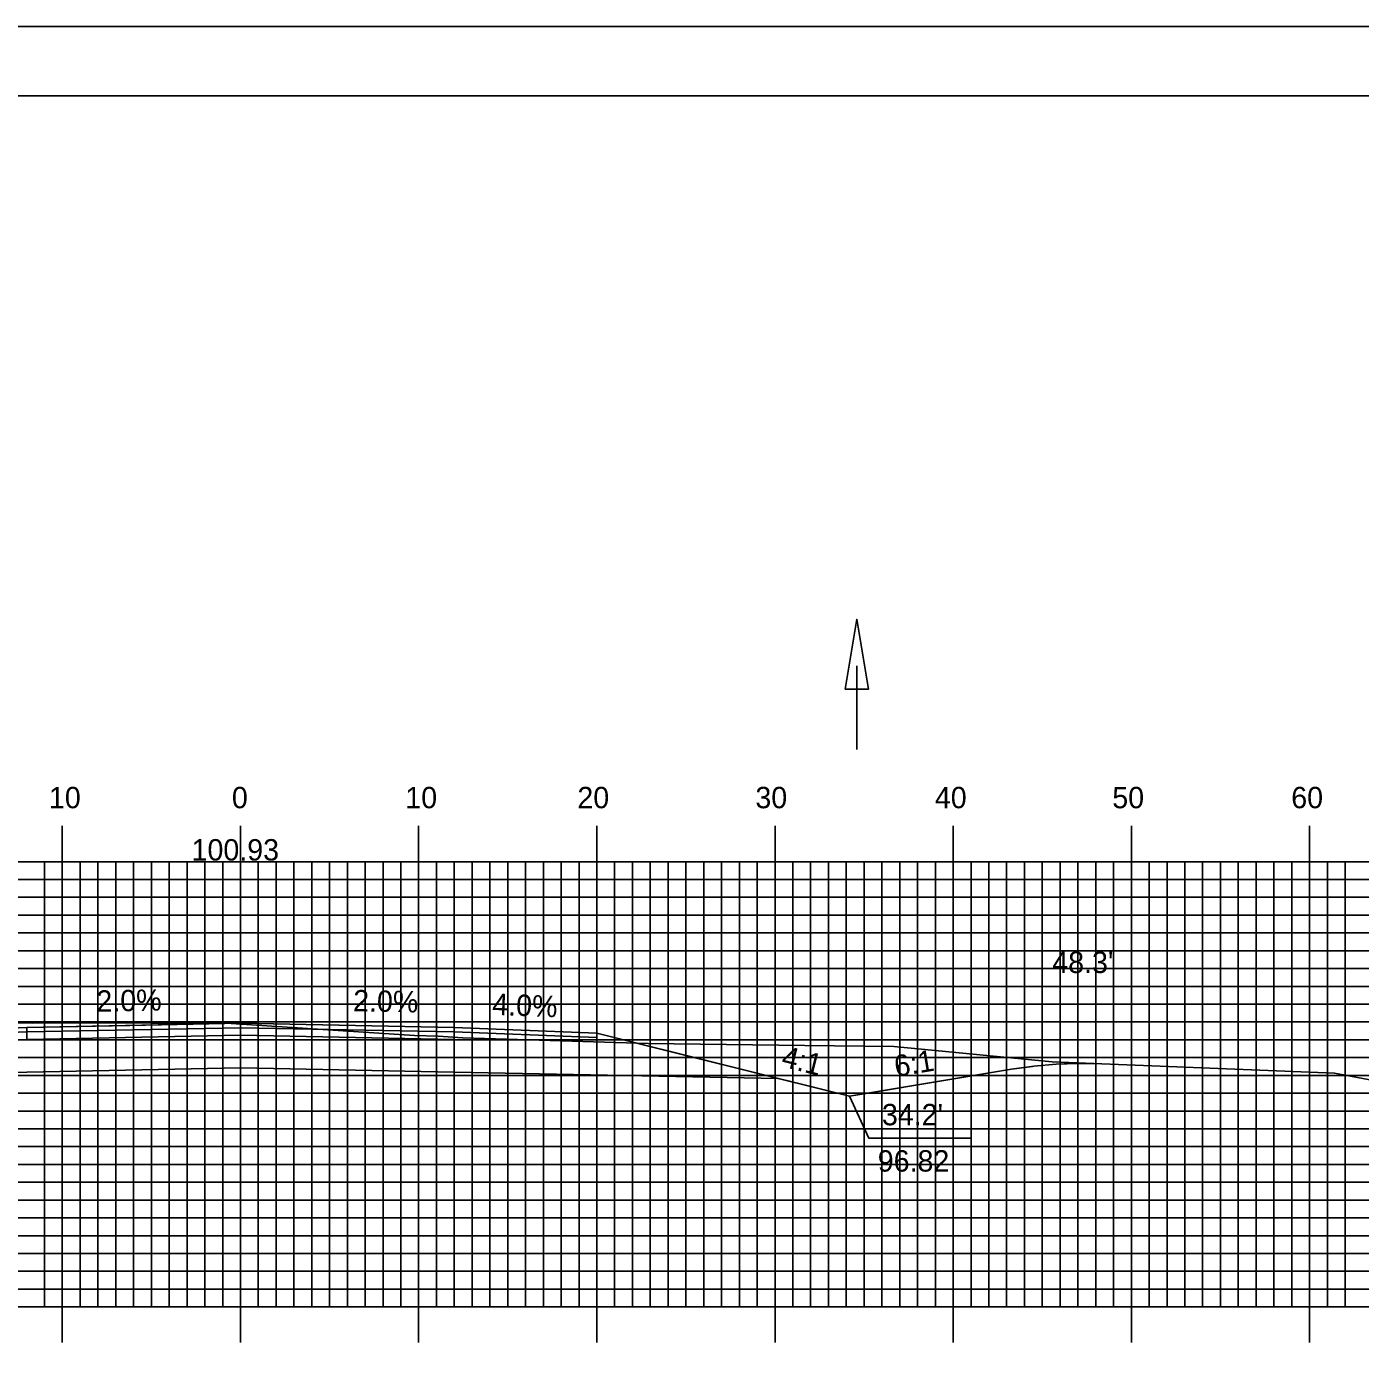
# Model space of a CAD drawing. Extents: x 1774777 to 1775120, y 442591 to 442811.
# Drawn here: x 1774930.7 to 1775005.5, y 442736.2 to 442810.5 of the extents above; entities that cross this region are included whole.
import ezdxf

# ---------------------------------------------------------------- set-up
doc = ezdxf.new("R2010")
doc.units = 0
for name, color, linetype in [('ANNOTATION', 7, 'Continuous'), ('BORDER', 7, 'Continuous'), ('D_Drainage_Ditch_Line', 7, 'Continuous'), ('D_Roadway_Centerline', 7, 'Continuous'), ('D_Roadway_Centerline_Text', 7, 'Continuous'), ('D_Roadway_Edge_Shoulder', 7, 'Continuous'), ('D_Roadway_Edge_TW', 7, 'Continuous'), ('D_Roadway_Pavement', 7, 'Continuous'), ('D_Roadway_SlopeLines', 7, 'Continuous'), ('D_Roadway_SubGrade', 7, 'Continuous'), ('D_Text_Standard', 7, 'Continuous'), ('H_V ANNOTATION', 7, 'Continuous'), ('MAJOR', 7, 'Continuous'), ('MINOR', 7, 'Continuous'), ('PLOT BOUNDARY', 7, 'Continuous'), ('S_Roadway_Centerline', 7, 'Continuous')]:
    doc.layers.add(name, color=color, linetype=linetype)

msp = doc.modelspace()

# ---------------------------------------------------------------- linework, layer by layer
at = {"layer": 'ANNOTATION'}
msp.add_lwpolyline([(1774983.643, 442748.137), (1774977.952, 442748.137), (1774976.859, 442750.49)], dxfattribs=at)
at = {"layer": 'BORDER'}
msp.add_lwpolyline([(1774793.085, 442596.665), (1775113.085, 442596.665), (1775113.085, 442806.665), (1774793.085, 442806.665)], close=True, dxfattribs=at)
at = {"layer": 'D_Drainage_Ditch_Line'}
msp.add_line((1774977.274, 442774.655), (1774977.274, 442769.956), dxfattribs=at)
msp.add_lwpolyline([(1774976.618, 442773.342), (1774977.93, 442773.342), (1774977.274, 442777.279)], close=True, dxfattribs=at)
at = {"layer": 'D_Roadway_Centerline'}
msp.add_lwpolyline([(1774922.685, 442754.034), (1774930.685, 442754.354), (1774936.47, 442754.47), (1774942.685, 442754.594), (1774947.294, 442754.502), (1774954.685, 442754.354), (1774962.685, 442754.034), (1774966.715, 442753.027), (1774972.859, 442751.49), (1774976.859, 442750.49), (1774977.909, 442750.665), (1774985.965, 442752.008), (1774987.141, 442752.173), (1774987.214, 442752.183), (1774988.464, 442752.294), (1774989.356, 442752.327), (1774989.715, 442752.34), (1774990.247, 442752.333), (1774990.964, 442752.322)], dxfattribs=at)
at = {"layer": 'D_Roadway_Edge_Shoulder'}
for points in [[(1774930.685, 442754.354), (1774922.685, 442754.034), (1774922.685, 442753.784), (1774930.685, 442754.104)], [(1774954.685, 442754.354), (1774962.685, 442754.034), (1774962.685, 442753.784), (1774954.685, 442754.104)]]:
    msp.add_lwpolyline(points, close=True, dxfattribs=at)
at = {"layer": 'D_Roadway_Edge_TW'}
msp.add_lwpolyline([(1774930.685, 442754.104), (1774930.685, 442754.354), (1774942.685, 442754.594), (1774954.685, 442754.354), (1774954.685, 442754.104), (1774942.685, 442754.344)], close=True, dxfattribs=at)
at = {"layer": 'D_Roadway_Pavement'}
msp.add_lwpolyline([(1774930.685, 442753.687), (1774930.685, 442754.104), (1774942.685, 442754.344), (1774954.685, 442754.104), (1774954.685, 442753.687), (1774942.685, 442753.927)], close=True, dxfattribs=at)
at = {"layer": 'D_Roadway_SlopeLines'}
for points in [[(1774962.685, 442754.034), (1774976.859, 442750.49)], [(1774976.859, 442750.49), (1774985.964, 442752.008), (1774987.214, 442752.183), (1774988.464, 442752.294), (1774989.715, 442752.34), (1774990.964, 442752.322)]]:
    msp.add_lwpolyline(points, dxfattribs=at)
at = {"layer": 'D_Roadway_SubGrade'}
msp.add_lwpolyline([(1774930.685, 442751.854), (1774912.511, 442751.49), (1774922.685, 442754.034), (1774922.685, 442753.784), (1774930.685, 442754.104), (1774942.685, 442754.344), (1774954.685, 442754.104), (1774962.685, 442753.784), (1774962.685, 442754.034), (1774972.859, 442751.49), (1774954.685, 442751.854), (1774942.685, 442752.094)], close=True, dxfattribs=at)
at = {"layer": 'MAJOR'}
for p, q in [((1774932.685, 442765.669), (1774932.685, 442763.665)), ((1774942.685, 442765.669), (1774942.685, 442763.665)), ((1774952.685, 442765.669), (1774952.685, 442763.665)), ((1774962.685, 442765.669), (1774962.685, 442763.665)), ((1774972.685, 442765.669), (1774972.685, 442763.665)), ((1774982.685, 442765.669), (1774982.685, 442763.665)), ((1774992.685, 442765.669), (1774992.685, 442763.665)), ((1775002.685, 442765.669), (1775002.685, 442763.665)), ((1774802.685, 442763.665), (1775082.685, 442763.665)), ((1774802.685, 442763.665), (1775082.685, 442763.665)), ((1774932.685, 442738.665), (1774932.685, 442763.665)), ((1774942.685, 442738.665), (1774942.685, 442763.665)), ((1774952.685, 442738.665), (1774952.685, 442763.665)), ((1774962.685, 442738.665), (1774962.685, 442763.665)), ((1774972.685, 442738.665), (1774972.685, 442763.665)), ((1774982.685, 442738.665), (1774982.685, 442763.665)), ((1774992.685, 442738.665), (1774992.685, 442763.665)), ((1775002.685, 442738.665), (1775002.685, 442763.665)), ((1774802.685, 442758.665), (1775082.685, 442758.665)), ((1774802.685, 442753.665), (1775082.685, 442753.665)), ((1774802.685, 442748.665), (1775082.685, 442748.665)), ((1774802.685, 442743.665), (1775082.685, 442743.665)), ((1774802.685, 442738.665), (1775082.685, 442738.665)), ((1774802.685, 442738.665), (1775082.685, 442738.665)), ((1774932.685, 442736.661), (1774932.685, 442738.665)), ((1774942.685, 442736.661), (1774942.685, 442738.665)), ((1774952.685, 442736.661), (1774952.685, 442738.665)), ((1774962.685, 442736.661), (1774962.685, 442738.665)), ((1774972.685, 442736.661), (1774972.685, 442738.665)), ((1774982.685, 442736.661), (1774982.685, 442738.665)), ((1774992.685, 442736.661), (1774992.685, 442738.665)), ((1775002.685, 442736.661), (1775002.685, 442738.665))]:
    msp.add_line(p, q, dxfattribs=at)
at = {"layer": 'MINOR'}
for p, q in [((1774931.685, 442738.665), (1774931.685, 442763.665)), ((1774933.685, 442738.665), (1774933.685, 442763.665)), ((1774934.685, 442738.665), (1774934.685, 442763.665)), ((1774935.685, 442738.665), (1774935.685, 442763.665)), ((1774936.685, 442738.665), (1774936.685, 442763.665)), ((1774937.685, 442738.665), (1774937.685, 442763.665)), ((1774938.685, 442738.665), (1774938.685, 442763.665)), ((1774939.685, 442738.665), (1774939.685, 442763.665)), ((1774940.685, 442738.665), (1774940.685, 442763.665)), ((1774941.685, 442738.665), (1774941.685, 442763.665)), ((1774943.685, 442738.665), (1774943.685, 442763.665)), ((1774944.685, 442738.665), (1774944.685, 442763.665)), ((1774945.685, 442738.665), (1774945.685, 442763.665)), ((1774946.685, 442738.665), (1774946.685, 442763.665)), ((1774947.685, 442738.665), (1774947.685, 442763.665)), ((1774948.685, 442738.665), (1774948.685, 442763.665)), ((1774949.685, 442738.665), (1774949.685, 442763.665)), ((1774950.685, 442738.665), (1774950.685, 442763.665)), ((1774951.685, 442738.665), (1774951.685, 442763.665)), ((1774953.685, 442738.665), (1774953.685, 442763.665)), ((1774954.685, 442738.665), (1774954.685, 442763.665)), ((1774955.685, 442738.665), (1774955.685, 442763.665)), ((1774956.685, 442738.665), (1774956.685, 442763.665)), ((1774957.685, 442738.665), (1774957.685, 442763.665)), ((1774958.685, 442738.665), (1774958.685, 442763.665)), ((1774959.685, 442738.665), (1774959.685, 442763.665)), ((1774960.685, 442738.665), (1774960.685, 442763.665)), ((1774961.685, 442738.665), (1774961.685, 442763.665)), ((1774963.685, 442738.665), (1774963.685, 442763.665)), ((1774964.685, 442738.665), (1774964.685, 442763.665)), ((1774965.685, 442738.665), (1774965.685, 442763.665)), ((1774966.685, 442738.665), (1774966.685, 442763.665)), ((1774967.685, 442738.665), (1774967.685, 442763.665)), ((1774968.685, 442738.665), (1774968.685, 442763.665)), ((1774969.685, 442738.665), (1774969.685, 442763.665)), ((1774970.685, 442738.665), (1774970.685, 442763.665)), ((1774971.685, 442738.665), (1774971.685, 442763.665)), ((1774973.685, 442738.665), (1774973.685, 442763.665)), ((1774974.685, 442738.665), (1774974.685, 442763.665)), ((1774975.685, 442738.665), (1774975.685, 442763.665)), ((1774976.685, 442738.665), (1774976.685, 442763.665)), ((1774977.685, 442738.665), (1774977.685, 442763.665)), ((1774978.685, 442738.665), (1774978.685, 442763.665)), ((1774979.685, 442738.665), (1774979.685, 442763.665)), ((1774980.685, 442738.665), (1774980.685, 442763.665)), ((1774981.685, 442738.665), (1774981.685, 442763.665)), ((1774983.685, 442738.665), (1774983.685, 442763.665)), ((1774984.685, 442738.665), (1774984.685, 442763.665)), ((1774985.685, 442738.665), (1774985.685, 442763.665)), ((1774986.685, 442738.665), (1774986.685, 442763.665)), ((1774987.685, 442738.665), (1774987.685, 442763.665)), ((1774988.685, 442738.665), (1774988.685, 442763.665)), ((1774989.685, 442738.665), (1774989.685, 442763.665)), ((1774990.685, 442738.665), (1774990.685, 442763.665)), ((1774991.685, 442738.665), (1774991.685, 442763.665)), ((1774993.685, 442738.665), (1774993.685, 442763.665)), ((1774994.685, 442738.665), (1774994.685, 442763.665)), ((1774995.685, 442738.665), (1774995.685, 442763.665)), ((1774996.685, 442738.665), (1774996.685, 442763.665)), ((1774997.685, 442738.665), (1774997.685, 442763.665)), ((1774998.685, 442738.665), (1774998.685, 442763.665)), ((1774999.685, 442738.665), (1774999.685, 442763.665)), ((1775000.685, 442738.665), (1775000.685, 442763.665)), ((1775001.685, 442738.665), (1775001.685, 442763.665)), ((1775003.685, 442738.665), (1775003.685, 442763.665)), ((1775004.685, 442738.665), (1775004.685, 442763.665)), ((1774802.685, 442762.665), (1775082.685, 442762.665)), ((1774802.685, 442761.665), (1775082.685, 442761.665)), ((1774802.685, 442760.665), (1775082.685, 442760.665)), ((1774802.685, 442759.665), (1775082.685, 442759.665)), ((1774802.685, 442757.665), (1775082.685, 442757.665)), ((1774802.685, 442756.665), (1775082.685, 442756.665)), ((1774802.685, 442755.665), (1775082.685, 442755.665)), ((1774802.685, 442754.665), (1775082.685, 442754.665)), ((1774802.685, 442752.665), (1775082.685, 442752.665)), ((1774802.685, 442751.665), (1775082.685, 442751.665)), ((1774802.685, 442750.665), (1775082.685, 442750.665)), ((1774802.685, 442749.665), (1775082.685, 442749.665)), ((1774802.685, 442747.665), (1775082.685, 442747.665)), ((1774802.685, 442746.665), (1775082.685, 442746.665)), ((1774802.685, 442745.665), (1775082.685, 442745.665)), ((1774802.685, 442744.665), (1775082.685, 442744.665)), ((1774802.685, 442742.665), (1775082.685, 442742.665)), ((1774802.685, 442741.665), (1775082.685, 442741.665)), ((1774802.685, 442740.665), (1775082.685, 442740.665)), ((1774802.685, 442739.665), (1775082.685, 442739.665))]:
    msp.add_line(p, q, dxfattribs=at)
at = {"layer": 'PLOT BOUNDARY'}
msp.add_lwpolyline([(1774776.898, 442590.547), (1775116.898, 442590.547), (1775116.898, 442810.547), (1774776.898, 442810.547)], close=True, dxfattribs=at)
at = {"layer": 'S_Roadway_Centerline'}
msp.add_lwpolyline([(1774862.901, 442755.252), (1774883.514, 442755.274), (1774884.255, 442755.26), (1774896.547, 442755.124), (1774906.351, 442754.769), (1774924.958, 442754.692), (1774928.821, 442754.634), (1774931.029, 442754.599), (1774933.217, 442754.609), (1774942.158, 442754.57), (1774952.453, 442753.909), (1774953.776, 442753.865), (1774955.155, 442753.783), (1774965.568, 442753.455), (1774974.355, 442753.345), (1774979.362, 442753.296), (1774988.238, 442752.434), (1775004.08, 442751.783), (1775012.235, 442750.261)], dxfattribs=at)

# ---------------------------------------------------------------- texts
at = {"layer": 'ANNOTATION'}
for s, rotation, p in [('2.0%', 1.14582, (1774934.612, 442755.233)), ('2.0%', 358.85424, (1774948.997, 442755.268)), ('4.0%', 357.70947, (1774956.797, 442755.071)), ('4:1', 345.96172, (1774972.983, 442752.18)), ('6:1', 9.46457, (1774979.484, 442751.574))]:
    msp.add_text(s, height=1.2, rotation=rotation, dxfattribs=at).set_placement(p)
for s, p in [("34.2'", (1774978.686, 442748.864)), ('96.82', (1774978.451, 442746.264))]:
    msp.add_text(s, height=1.2, dxfattribs=at).set_placement(p)
at = {"layer": 'D_Roadway_Centerline'}
for s, p in [('C', (1774942.679, 442754.594)), ('L', (1774942.685, 442754.587))]:
    msp.add_text(s, height=0.0146, dxfattribs=at).set_placement(p)
at = {"layer": 'D_Roadway_Centerline_Text'}
msp.add_text('100.93', height=1.2, dxfattribs=at).set_placement((1774939.94, 442763.73))
at = {"layer": 'D_Text_Standard'}
msp.add_text("48.3'", height=1.2, dxfattribs=at).set_placement((1774988.246, 442757.414))
at = {"layer": 'H_V ANNOTATION'}
for s, p in [('10', (1774931.936, 442766.665)), ('0', (1774942.203, 442766.665)), ('10', (1774951.936, 442766.665)), ('20', (1774961.593, 442766.665)), ('30', (1774971.583, 442766.665)), ('40', (1774981.657, 442766.665)), ('50', (1774991.614, 442766.665)), ('60', (1775001.657, 442766.665))]:
    msp.add_text(s, height=1.2, dxfattribs=at).set_placement(p)

doc.saveas('drawing.dxf')
